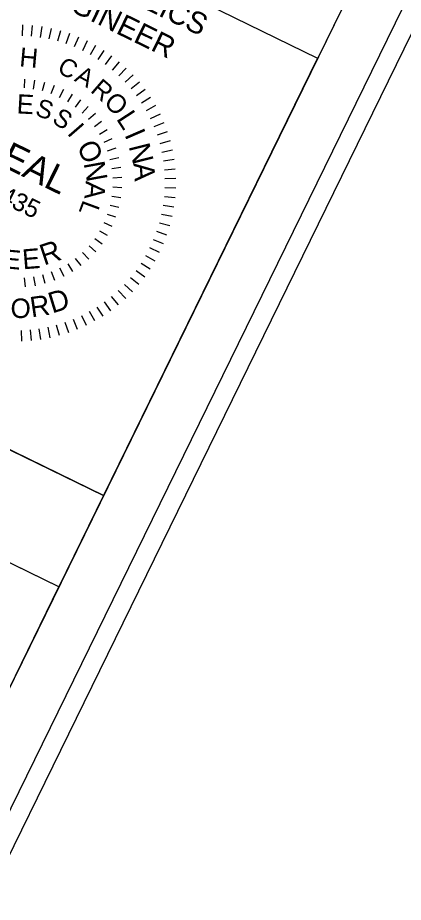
# Model space of a CAD drawing. Extents: x 1519210 to 1521378, y 637447 to 639183.
# Drawn here: x 1521092.4 to 1521181.5, y 638201.7 to 638406.2 of the extents above; entities that cross this region are included whole.
import ezdxf

# ---------------------------------------------------------------- set-up
doc = ezdxf.new("R2010")
doc.units = 0
for name, color, linetype in [('Default', 7, 'Continuous'), ('Prop Paved Shoulder', 7, 'Continuous'), ('Sheet Plan CELL', 7, 'Continuous'), ('Sheet Plan Layout CELL', 7, 'Continuous'), ('Sheet Plot Border Inside CELL', 7, 'Continuous'), ('Sheet Plot Border Outside CELL', 7, 'Continuous'), ('Sheet Sticker Exception Certification CELL', 7, 'Continuous')]:
    doc.layers.add(name, color=color, linetype=linetype)

msp = doc.modelspace()

# ---------------------------------------------------------------- linework, layer by layer
at = {"layer": 'Default'}
msp.add_lwpolyline([(1520906.34, 638330.09), (1521086.04, 638242.2), (1521101.9, 638274.63), (1520922.2, 638362.52)], close=True, dxfattribs=at)
at = {"layer": 'Prop Paved Shoulder'}
for p, q in [((1521093.57, 638404.52), (1521093.48, 638402.03)), ((1521095.77, 638404.39), (1521095.54, 638401.9)), ((1521097.96, 638404.12), (1521097.58, 638401.65)), ((1521100.14, 638403.71), (1521099.6, 638401.28)), ((1521102.28, 638403.18), (1521101.6, 638400.78)), ((1521104.38, 638402.51), (1521103.56, 638400.16)), ((1521106.44, 638401.72), (1521105.48, 638399.42)), ((1521108.46, 638400.81), (1521107.36, 638398.57)), ((1521110.41, 638399.78), (1521109.18, 638397.61)), ((1521112.3, 638398.63), (1521110.94, 638396.54)), ((1521114.11, 638397.37), (1521112.63, 638395.37)), ((1521115.85, 638396.01), (1521114.25, 638394.1)), ((1521117.5, 638394.54), (1521115.78, 638392.72)), ((1521094.03, 638392.02), (1521093.88, 638389.95)), ((1521096.34, 638391.75), (1521096, 638389.7)), ((1521119.05, 638392.97), (1521117.23, 638391.27)), ((1521098.62, 638391.25), (1521098.08, 638389.25)), ((1521100.83, 638390.54), (1521100.1, 638388.6)), ((1521102.97, 638389.62), (1521102.06, 638387.76)), ((1521102.06, 638387.76), (1521102.97, 638389.62)), ((1521120.51, 638391.31), (1521118.6, 638389.72)), ((1521121.87, 638389.57), (1521119.86, 638388.1)), ((1521105.01, 638388.49), (1521103.92, 638386.73)), ((1521123.12, 638387.75), (1521121.02, 638386.41)), ((1521106.93, 638387.18), (1521105.68, 638385.52)), ((1521108.71, 638385.68), (1521107.31, 638384.16)), ((1521124.26, 638385.86), (1521122.09, 638384.64)), ((1521110.35, 638384.02), (1521108.8, 638382.64)), ((1521125.28, 638383.9), (1521123.04, 638382.81)), ((1521111.81, 638382.21), (1521110.14, 638380.98)), ((1521126.18, 638381.88), (1521123.88, 638380.94)), ((1521113.1, 638380.27), (1521111.31, 638379.21)), ((1521126.96, 638379.82), (1521124.6, 638379.01)), ((1521114.18, 638378.21), (1521112.3, 638377.33)), ((1521127.61, 638377.71), (1521125.21, 638377.04)), ((1521115.07, 638376.06), (1521113.11, 638375.36)), ((1521128.13, 638375.56), (1521125.7, 638375.04)), ((1521115.74, 638373.83), (1521113.73, 638373.32)), ((1521128.53, 638373.39), (1521126.06, 638373.02)), ((1521116.2, 638371.54), (1521114.14, 638371.23)), ((1521128.79, 638371.19), (1521126.3, 638370.97)), ((1521116.43, 638369.23), (1521114.36, 638369.12)), ((1521128.91, 638368.99), (1521126.42, 638368.92)), ((1521116.44, 638366.9), (1521114.36, 638366.99)), ((1521116.22, 638364.58), (1521114.16, 638364.88)), ((1521128.9, 638366.78), (1521126.42, 638366.86)), ((1521115.78, 638362.29), (1521113.76, 638362.78)), ((1521128.77, 638364.57), (1521126.29, 638364.81)), ((1521115.12, 638360.06), (1521113.16, 638360.74)), ((1521128.09, 638360.21), (1521125.66, 638360.74)), ((1521128.5, 638362.38), (1521126.03, 638362.77)), ((1521114.25, 638357.9), (1521112.37, 638358.77)), ((1521127.56, 638358.07), (1521125.16, 638358.74)), ((1521113.18, 638355.83), (1521111.38, 638356.88)), ((1521126.89, 638355.96), (1521124.54, 638356.78)), ((1521110.26, 638355.16), (1521111.95, 638353.95)), ((1521126.11, 638353.9), (1521123.81, 638354.86)), ((1521110.45, 638352.06), (1521108.9, 638353.43)), ((1521125.19, 638351.89), (1521122.96, 638352.98)), ((1521107.06, 638348.89), (1521105.79, 638350.53)), ((1521108.83, 638350.39), (1521107.41, 638351.9)), ((1521124.16, 638349.93), (1521121.99, 638351.16)), ((1521105.15, 638347.56), (1521104.04, 638349.31)), ((1521123.01, 638348.05), (1521120.93, 638349.4)), ((1521098.78, 638344.75), (1521098.22, 638346.75)), ((1521100.98, 638345.48), (1521100.24, 638347.42)), ((1521103.12, 638346.41), (1521102.19, 638348.27)), ((1521121.76, 638346.23), (1521119.75, 638347.71)), ((1521094.19, 638343.95), (1521094.03, 638346.03)), ((1521096.5, 638344.24), (1521096.14, 638346.29)), ((1521118.92, 638342.85), (1521117.11, 638344.56)), ((1521120.39, 638344.5), (1521118.48, 638346.1)), ((1521117.36, 638341.29), (1521115.65, 638343.11)), ((1521113.96, 638338.47), (1521112.48, 638340.49)), ((1521115.7, 638339.83), (1521114.1, 638341.75)), ((1521110.24, 638336.09), (1521109.02, 638338.26)), ((1521112.13, 638337.22), (1521110.79, 638339.32)), ((1521106.26, 638334.16), (1521105.32, 638336.47)), ((1521108.28, 638335.07), (1521107.2, 638337.31)), ((1521097.77, 638331.82), (1521097.4, 638334.28)), ((1521099.94, 638332.21), (1521099.43, 638334.65)), ((1521102.09, 638332.74), (1521101.42, 638335.14)), ((1521104.2, 638333.39), (1521103.39, 638335.74)), ((1521093.37, 638331.43), (1521093.3, 638333.92)), ((1521095.58, 638331.56), (1521095.35, 638334.04))]:
    msp.add_line(p, q, dxfattribs=at)
at = {"layer": 'Sheet Plan CELL'}
for points in [[(1521178.17, 638430.52), (1519830.66, 639089.56), (1519369.35, 638146.33), (1520716.83, 637487.3)], [(1521071.81, 638440.72), (1521161.64, 638396.81), (1521112.22, 638295.73), (1521022.38, 638339.65)]]:
    msp.add_lwpolyline(points, close=True, dxfattribs=at)
at = {"layer": 'Sheet Plan Layout CELL'}
msp.add_lwpolyline([(1520870.3, 638345.67), (1521085.24, 638240.54), (1521178.18, 638430.52), (1520963.21, 638535.65)], close=True, dxfattribs=at)
at = {"layer": 'Sheet Plot Border Inside CELL'}
msp.add_lwpolyline([(1519230.36, 638211.5), (1520726.95, 637479.57), (1521190.47, 638427.28), (1519693.87, 639159.23)], close=True, dxfattribs=at)
at = {"layer": 'Sheet Plot Border Outside CELL'}
msp.add_lwpolyline([(1519209.9, 638199.25), (1520722.21, 637459.61), (1521203.3, 638443.27), (1519690.98, 639182.91)], close=True, dxfattribs=at)
at = {"layer": 'Sheet Sticker Exception Certification CELL'}
for p, q in [((1520932.53, 638383.63), (1521112.22, 638295.74)), ((1520932.53, 638383.63), (1521112.22, 638295.74)), ((1521101.9, 638274.63), (1520922.2, 638362.52)), ((1521101.9, 638274.63), (1520922.2, 638362.52)), ((1521112.22, 638295.73), (1521101.89, 638274.62)), ((1521112.22, 638295.73), (1521101.89, 638274.62))]:
    msp.add_line(p, q, dxfattribs=at)

# ---------------------------------------------------------------- texts
at = {"layer": 'Prop Paved Shoulder'}
for s, height, rotation, p in [('H', 4.4, 354.9524, (1521092.7, 638394.97)), ('C', 4.15, 331.2417, (1521101.29, 638393.73)), ('A', 4.15, 331.2417, (1521105.32, 638391.66)), ('R', 4.28, 319.2324, (1521109, 638389.17)), ('E', 4.44, 356.8291, (1521092.11, 638384.09)), ('S', 4.19, 341.5328, (1521096.24, 638383.66)), ('O', 4.34, 316.1756, (1521112.09, 638386.33)), ('S', 4.19, 326.2366, (1521100.11, 638382.14)), ('L', 4.61, 303.0393, (1521115.07, 638382.81)), ('I', 4.44, 310.9403, (1521103.68, 638379.4)), ('SEAL', 6.23, 333.8847, (1521083.16, 638374.57)), ('I', 4.78, 293.4638, (1521117.01, 638379.18)), ('O', 4.75, 295.6441, (1521105.97, 638376.47)), ('N', 4.86, 284.1693, (1521118.02, 638376.5)), ('047435', 4.15, 333.8847, (1521079.66, 638367.79)), ('N', 4.85, 280.3478, (1521107.62, 638372.57)), ('A', 4.8, 274.4018, (1521119.13, 638372.55)), ('A', 4.6, 265.0516, (1521108.17, 638368.52)), ('L', 4.2, 249.7554, (1521107.56, 638364.23)), ('E', 4.39, 354.6926, (1521089.05, 638348.3)), ('E', 4.61, 4.6785, (1521093.66, 638348.02)), ('R', 4.83, 18.4496, (1521098.48, 638348.88)), ('D', 4.82, 17.2091, (1521100.38, 638337.81)), ('O', 4.5, 359.5039, (1521090.75, 638336.8)), ('R', 4.68, 8.3265, (1521095.62, 638336.93))]:
    msp.add_text(s, height=height, rotation=rotation, dxfattribs=at).set_placement(p)
at = {"layer": 'Sheet Plan CELL'}
for s, p in [('HYDRAULICS', (1521095.98, 638420.81)), ('ENGINEER', (1521095.86, 638412))]:
    msp.add_text(s, height=5, rotation=333.9377, dxfattribs=at).set_placement(p)

doc.saveas('drawing.dxf')
